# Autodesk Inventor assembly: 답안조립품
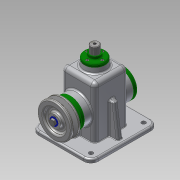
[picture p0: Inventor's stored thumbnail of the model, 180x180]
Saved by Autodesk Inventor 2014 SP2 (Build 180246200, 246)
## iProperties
Created: 2016-08
Part Number: 답안조립품
Document SubType Name: Assembly
Designer: user
Author: user
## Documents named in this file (19)
- C:\Users\user\Desktop\460820V1010\답안조립품.iam
- C:\Users\user\Desktop\460820V1010\본체.ipt
- C:\Users\user\Desktop\460820V1010\V-벨트풀리.ipt
- C:\Users\user\Desktop\460820V1010\고정핀.ipt
- C:\Users\user\Desktop\460820V1010\뒤커버.ipt
- C:\Users\user\Desktop\460820V1010\링크.ipt
- C:\Users\user\Desktop\460820V1010\멈춤링 6 x 5.ipt
- C:\Users\user\Desktop\460820V1010\멈춤링 15 x 1.ipt
- C:\Users\user\Desktop\460820V1010\베어링 15 x 35 x 11.ipt
- C:\Users\user\Desktop\460820V1010\볼트 M3 x 8.ipt
- C:\Users\user\Desktop\460820V1010\볼트 M4 x 10.ipt
- C:\Users\user\Desktop\460820V1010\볼트 M6 x 12.ipt
- C:\Users\user\Desktop\460820V1010\상부부시.ipt
- C:\Users\user\Desktop\460820V1010\슬라이드바.ipt
- C:\Users\user\Desktop\460820V1010\앞커버.ipt
- C:\Users\user\Desktop\460820V1010\오일실 15 25 7.ipt
- C:\Users\user\Desktop\460820V1010\와셔.ipt
- C:\Users\user\Desktop\460820V1010\키 5 x 5 x 14.ipt
- C:\Users\user\Desktop\460820V1010\편심축.ipt
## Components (15 placed, 5 different names)
1. V-벨트풀리:1 — 각도:1
2. 고정핀:1 — 강체:4, 강체:5, 각도:2
3. ISO 4018 M6 x 12:1 — 강체:2
4. ISO 4762 M4 x 10:1 — 강체:6
5. ISO 4762 M4 x 10:3
6. ISO 4762 M4 x 10:4
7. ISO 4762 M4 x 10:5
8. ISO 4762 M4 x 10:2 — 강체:7
9. ISO 4762 M4 x 10:6
10. ISO 4762 M4 x 10:7
11. ISO 4762 M4 x 10:8
12. ISO 4762 M3 x 8:1 — 강체:8
13. ISO 4762 M3 x 8:2
14. ISO 4762 M3 x 8:3
15. ISO 4762 M3 x 8:4
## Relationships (8: WeldJoint 6, Angle 2)
- 각도:1 [Angle]: V-벨트풀리:1
- 강체:2 [WeldJoint]: ISO 4018 M6 x 12:1
- 강체:4 [WeldJoint]: 고정핀:1
- 강체:5 [WeldJoint]: 고정핀:1
- 각도:2 [Angle]: 고정핀:1
- 강체:6 [WeldJoint]: ISO 4762 M4 x 10:1
- 강체:7 [WeldJoint]: ISO 4762 M4 x 10:2
- 강체:8 [WeldJoint]: ISO 4762 M3 x 8:1
